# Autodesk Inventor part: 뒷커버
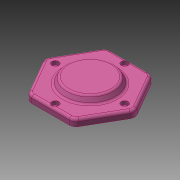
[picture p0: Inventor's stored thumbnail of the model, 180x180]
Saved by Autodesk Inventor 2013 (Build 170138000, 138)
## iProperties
Created: 2013-02
Part Number: 뒷커버
Document SubType Name: Modeling
Density: 1 g/cm^3
Material: 일반
Author: 한국산업디자인학원[gmhk.co.kr]
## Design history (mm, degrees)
sketch "스케치1" dims "d37" = 105
  geometry: L1 (50.191, -4)-(28.559, -41.466); L2 (21.631, -45.466)-(-21.631, -45.466); L3 (-28.559, -41.466)-(-50.191, -4); L4 (-50.191, 4)-(-28.559, 41.466); L5 (-21.631, 45.466)-(21.631, 45.466); L6 (28.559, 41.466)-(50.191, 4); C1 r 30 at (0, 0); A1 r 8 centre (-21.631, 37.466) between (-21.631, 45.466) and (-28.559, 41.466); A2 r 8 centre (21.631, 37.466) between (28.559, 41.466) and (21.631, 45.466); A3 r 8 centre (43.262, 0) between (50.191, -4) and (50.191, 4); A4 r 8 centre (21.631, -37.466) between (21.631, -45.466) and (28.559, -41.466); A5 r 8 centre (-21.631, -37.466) between (-28.559, -41.466) and (-21.631, -45.466); A6 r 8 centre (-43.262, 0) between (-50.191, 4) and (-50.191, -4); 9 further points
  constraints: 12 end point, 12 point on circle, 12 point on line, 12 tangent, 7 centre point, 5 equal radius, 3 coincident, 1 horizontal, 1 horizontal alignment, 15 other
  dimensions: "d39" = 60 diameter of C1; "d40" = 8 radius of A1
extrude "돌출1" new body sketch "스케치1" distance "d0" = 8; taper "d1" = 0 deg
sketch "스케치2"
  geometry: C1 r 30 at (0, 0); 1 further point
  constraints: 1 centre point, 1 coincident
  dimensions: "d2" = 60 diameter of C1
extrude "돌출2" join sketch "스케치2" distance "d3" = 7; taper "d4" = -30 deg
sketch "스케치3"
  geometry: C1 r 30 at (0, 0) reference; A1 r 40 centre (0, 0) between (0, 40) and (-40, 0); 2 further points
  constraints: 4 point on circle, 2 horizontal alignment, 2 vertical alignment, 1 centre point, 1 coincident
  dimensions: "d47" = 80 diameter of A1
hole "구멍2" sketch "스케치3" at (0, 40), (-40, 0), (0, -40), (40, 0) diameter "d14" = 4.5; stored, may be unused: countersink angle "d18" = 90 deg, drill point angle "d20" = 118 deg; dims "d15" = 6, "d16" = 8, "d17" = 4.4, "d19" = 20
extrude "돌출3" join sketch "스케치1" distance "d21" = 12; taper "d22" = 0 deg
hole "구멍3" diameter "d25" = 30; stored, may be unused: countersink angle "d29" = 90 deg, drill point angle "d31" = 0 deg; dims "d26" = 6, "d27" = 42, "d28" = 13, "d30" = 16, "d50" = 10, "d51" = 10
fillet "모깎기1" dims "d32" = 3, "d33" = 1
chamfer "모따기1" distance "d34" = 1; stored, may be unused: second distance "d35" = 2, angle "d36" = 45 deg
chamfer "모따기2" distance "d43" = 1; stored, may be unused: second distance "d44" = 2, angle "d45" = 45 deg
fillet "모깎기2" dims "d46" = 3
node "솔리드1"
